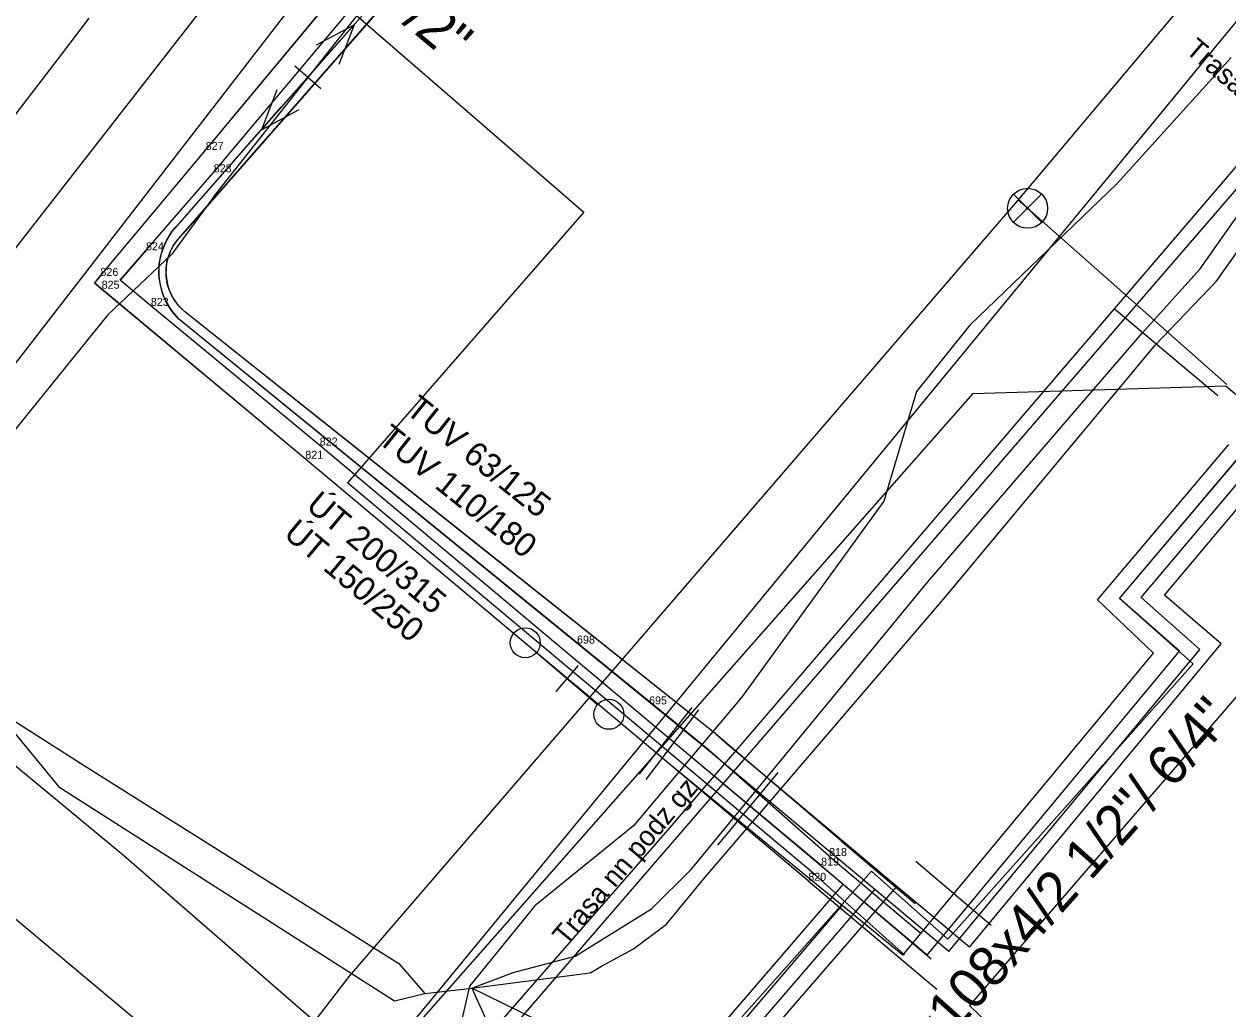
# Model space of a CAD drawing. Extents: x -494395 to -49419, y -1126982 to -112683.
# Drawn here: x -494321.11 to -494291.02, y -1126865.03 to -1126840.42 of the extents above; entities that cross this region are included whole.
import ezdxf

# ---------------------------------------------------------------- set-up
doc = ezdxf.new("R2010")
doc.units = 0
for name, color, linetype in [('Vrstva 1', 7, 'Continuous'), ('Vrstva 11', 7, 'Continuous'), ('Vrstva 12', 7, 'Continuous'), ('Vrstva 20', 7, 'Continuous'), ('Vrstva 22', 7, 'Continuous'), ('Vrstva 35', 7, 'Continuous'), ('Vrstva 37', 7, 'Continuous'), ('Vrstva 41', 7, 'Continuous'), ('Vrstva 45', 7, 'Continuous'), ('Vrstva 49', 7, 'Continuous'), ('Vrstva 5', 7, 'Continuous'), ('Vrstva 9', 7, 'Continuous')]:
    doc.layers.add(name, color=color, linetype=linetype)

msp = doc.modelspace()

# ---------------------------------------------------------------- linework, layer by layer
at = {"layer": 'Vrstva 1'}
msp.add_line((-494291.28, -1126849.71), (-494293.87, -1126847.53), dxfattribs=at)
for points in [[(-494360.93, -1126825.46), (-494336.61, -1126847.07), (-494335.52, -1126848.04), (-494331.63, -1126851.49), (-494328.43, -1126854.34), (-494326.87, -1126852.55), (-494322.66, -1126847.73), (-494316.57, -1126839.92), (-494313.81, -1126836.37), (-494313.37, -1126835.81), (-494312.74, -1126831.04), (-494296.98, -1126813.46), (-494295.26, -1126811.1), (-494294.71, -1126810.42), (-494294.273, -1126809.878)], [(-494274.427, -1126824.329), (-494280.54, -1126831.95), (-494293.87, -1126847.53), (-494302.1, -1126857.15), (-494305.03, -1126860.56), (-494313.03, -1126869.73)], [(-494328.43, -1126854.34), (-494329.69, -1126855.78), (-494325.53, -1126859.26), (-494313.03, -1126869.73), (-494305.67, -1126875.89), (-494291.14, -1126888.24), (-494277.78, -1126899.58), (-494263.78, -1126911.3)]]:
    msp.add_lwpolyline(points, dxfattribs=at)
at = {"layer": 'Vrstva 11'}
for points in [[(-494355.1, -1126829.18), (-494344.74, -1126839.16), (-494336.23, -1126846.61), (-494318.62, -1126861.19), (-494312.35, -1126866.64), (-494297.39, -1126849.65), (-494291.08, -1126849.46), (-494282.68, -1126856.57), (-494286.52, -1126861.18)], [(-494287.06, -1126860.73), (-494274.54, -1126845.74), (-494282.39, -1126839.2), (-494284.71, -1126837.46), (-494309.28, -1126865.93)], [(-494305.88, -1126863.53), (-494305.05, -1126862.91), (-494304.09, -1126861.74), (-494301.68, -1126858.93), (-494298.13, -1126854.79), (-494293.99, -1126849.82), (-494292.84, -1126848.44), (-494291.32, -1126846.85), (-494288.75, -1126843.24)], [(-494321.87, -1126857.51), (-494320.24, -1126859.48), (-494311.85, -1126864.83), (-494311.09, -1126864.65)], [(-494306.68, -1126863.96), (-494305.88, -1126863.53)], [(-494309.92, -1126864.51), (-494306.96, -1126864.13), (-494306.68, -1126863.96)], [(-494309.92, -1126864.51), (-494309.28, -1126865.93)], [(-494307.98, -1126865.46), (-494309.92, -1126864.51)]]:
    msp.add_lwpolyline(points, dxfattribs=at)
at = {"layer": 'Vrstva 12'}
for points in [[(-494309.92, -1126864.51), (-494308.89, -1126864.12), (-494307.34, -1126863.71), (-494305.43, -1126862.53), (-494304.44, -1126861.55), (-494302.04, -1126858.63), (-494298.52, -1126854.36), (-494294.37, -1126849.53), (-494293.17, -1126848.14), (-494291.72, -1126846.53), (-494289.12, -1126842.84), (-494287.01, -1126840.81), (-494284.04, -1126837.24), (-494280.15, -1126832.84), (-494279.04, -1126831.59), (-494278.24, -1126830.51), (-494275.18, -1126826.51), (-494273.746, -1126824.825)], [(-494321.87, -1126857.51), (-494319.61, -1126858.95)], [(-494319.61, -1126858.95), (-494311.74, -1126863.9)], [(-494311.74, -1126863.9), (-494311.09, -1126864.65)], [(-494311.09, -1126864.65), (-494309.92, -1126864.51)]]:
    msp.add_lwpolyline(points, dxfattribs=at)
at = {"layer": 'Vrstva 20'}
for points in [[(-494292.524, -1126811.151), (-494292.619, -1126811.279), (-494299.712, -1126820.924), (-494325.277, -1126853.999), (-494328.623, -1126858.84)], [(-494316.901, -1126869.31), (-494312.976, -1126864.212), (-494296.263, -1126844.814), (-494282.714, -1126828.712), (-494277.399, -1126822.165)], [(-494291.048, -1126849.423), (-494296.03, -1126845.02), (-494296.263, -1126844.814)]]:
    msp.add_lwpolyline(points, dxfattribs=at)
at = {"layer": 'Vrstva 22'}
for p, q in [((-494296.38, -1126845.37), (-494295.68, -1126844.67)), ((-494295.68, -1126845.37), (-494296.38, -1126844.67))]:
    msp.add_line(p, q, dxfattribs=at)
for radius in [0.5, 0.025]:
    msp.add_circle((-494296.03, -1126845.02), radius, dxfattribs=at)
at = {"layer": 'Vrstva 35'}
msp.add_lwpolyline([(-494300.66, -1126826.53), (-494304.08, -1126829.77), (-494307, -1126833.05), (-494310.38, -1126837.7), (-494312.57, -1126839.92), (-494316.3, -1126844.63), (-494317.42, -1126846.17), (-494319.02, -1126847.69), (-494327.08, -1126857.66), (-494327.96, -1126857.89), (-494330.7, -1126861.76), (-494332.02, -1126864.51), (-494334.7, -1126868.68), (-494331.75, -1126870.74), (-494343.19, -1126889.21), (-494346.12, -1126887.28)], dxfattribs=at)
at = {"layer": 'Vrstva 37'}
msp.add_lwpolyline([(-494267.04, -1126829.708), (-494297.48, -1126864.95), (-494274.68, -1126887.05), (-494269.33, -1126885.62)], dxfattribs=at)
at = {"layer": 'Vrstva 41'}
msp.add_lwpolyline([(-494276.436, -1126822.866), (-494276.44, -1126822.87), (-494321.46, -1126877.59)], dxfattribs=at)
at = {"layer": 'Vrstva 45'}
for p, q in [((-494316.57, -1126843.56), (-494308.89, -1126834.33)), ((-494316.57, -1126843.56), (-494308.89, -1126834.34)), ((-494316.37, -1126844.12), (-494308.66, -1126834.92)), ((-494316.37, -1126844.12), (-494308.66, -1126834.92)), ((-494314.68, -1126842.49), (-494308.31, -1126835.27)), ((-494312.93, -1126840.85), (-494308.15, -1126835.39)), ((-494310.93, -1126838.57), (-494317.14, -1126845.66)), ((-494313.94, -1126839.21), (-494307.12, -1126845.12)), ((-494315.175, -1126843.055), (-494312.86, -1126840.43)), ((-494317.14, -1126845.66), (-494312.93, -1126840.85)), ((-494314.339, -1126841.459), (-494313.696, -1126842.028)), ((-494317.22, -1126845.38), (-494314.68, -1126842.49)), ((-494317.22, -1126845.38), (-494315.23, -1126843.12)), ((-494319.2, -1126846.71), (-494316.57, -1126843.56)), ((-494319.2, -1126846.71), (-494316.57, -1126843.56)), ((-494316.57, -1126843.56), (-494316.57, -1126843.56)), ((-494318.06, -1126846.07), (-494316.37, -1126844.12)), ((-494318.06, -1126846.07), (-494316.37, -1126844.12)), ((-494316.37, -1126844.12), (-494316.37, -1126844.12)), ((-494307.4, -1126844.64), (-494307.4, -1126844.64)), ((-494307.12, -1126845.12), (-494313.03, -1126851.88)), ((-494317.56, -1126845.85), (-494317.41, -1126845.6)), ((-494317.41, -1126845.6), (-494317.22, -1126845.38)), ((-494317.27, -1126845.8), (-494317.14, -1126845.66)), ((-494317.25, -1126845.4), (-494317.25, -1126845.4)), ((-494317.14, -1126845.66), (-494317.14, -1126845.66)), ((-494317.67, -1126846.12), (-494317.56, -1126845.85)), ((-494317.47, -1126846.13), (-494317.38, -1126845.96)), ((-494317.38, -1126845.96), (-494317.27, -1126845.8)), ((-494307.8, -1126845.9), (-494307.8, -1126845.9)), ((-494318.06, -1126846.07), (-494318.71, -1126846.82)), ((-494318.71, -1126846.82), (-494318.06, -1126846.07)), ((-494318.06, -1126846.07), (-494318.06, -1126846.07)), ((-494317.73, -1126846.41), (-494317.67, -1126846.12)), ((-494317.53, -1126846.32), (-494317.47, -1126846.13)), ((-494317.74, -1126846.7), (-494317.73, -1126846.41)), ((-494317.56, -1126846.51), (-494317.53, -1126846.32)), ((-494317.56, -1126846.7), (-494317.56, -1126846.51)), ((-494319.2, -1126846.71), (-494319.35, -1126846.88)), ((-494319.35, -1126846.89), (-494319.2, -1126846.71)), ((-494319.2, -1126846.71), (-494319.2, -1126846.71)), ((-494317.94, -1126847.46), (-494318.71, -1126846.82)), ((-494318.71, -1126846.82), (-494318.71, -1126846.82)), ((-494317.94, -1126847.46), (-494318.71, -1126846.82)), ((-494317.74, -1126846.7), (-494317.74, -1126846.7)), ((-494317.7, -1126846.94), (-494317.74, -1126846.7)), ((-494317.56, -1126846.7), (-494317.56, -1126846.7)), ((-494317.53, -1126846.91), (-494317.56, -1126846.7)), ((-494319.17, -1126847.03), (-494319.35, -1126846.88)), ((-494319.35, -1126846.88), (-494319.35, -1126846.88)), ((-494319.17, -1126847.04), (-494319.35, -1126846.89)), ((-494319.17, -1126847.03), (-494319.17, -1126847.03)), ((-494314.08, -1126851.28), (-494319.17, -1126847.03)), ((-494314.08, -1126851.28), (-494319.17, -1126847.04)), ((-494317.64, -1126847.17), (-494317.7, -1126846.94)), ((-494317.54, -1126847.4), (-494317.64, -1126847.17)), ((-494317.47, -1126847.1), (-494317.53, -1126846.91)), ((-494317.37, -1126847.29), (-494317.47, -1126847.1)), ((-494313.72, -1126850.95), (-494317.94, -1126847.46)), ((-494317.94, -1126847.46), (-494317.94, -1126847.46)), ((-494313.72, -1126850.95), (-494317.94, -1126847.46)), ((-494317.41, -1126847.6), (-494317.54, -1126847.4)), ((-494317.25, -1126847.45), (-494317.37, -1126847.29)), ((-494317.1, -1126847.6), (-494317.25, -1126847.45)), ((-494317.25, -1126847.78), (-494317.41, -1126847.6)), ((-494303.89, -1126858.11), (-494317.1, -1126847.6)), ((-494317.1, -1126847.6), (-494317.1, -1126847.6)), ((-494309.74, -1126853.46), (-494317.1, -1126847.6)), ((-494304.06, -1126858.51), (-494317.25, -1126847.78)), ((-494317.25, -1126847.78), (-494317.25, -1126847.78)), ((-494304.06, -1126858.52), (-494317.25, -1126847.78)), ((-494313.72, -1126850.95), (-494313.72, -1126850.95)), ((-494304.52, -1126858.66), (-494313.72, -1126850.95)), ((-494304.52, -1126858.66), (-494313.72, -1126850.95)), ((-494312.25, -1126850.99), (-494312.25, -1126850.99)), ((-494294.28, -1126854.81), (-494291, -1126850.92)), ((-494293.73, -1126854.77), (-494290.45, -1126850.89)), ((-494293.19, -1126854.75), (-494289.91, -1126850.85)), ((-494292.61, -1126854.69), (-494289.36, -1126850.82)), ((-494314.08, -1126851.28), (-494314.08, -1126851.28)), ((-494308.95, -1126855.58), (-494314.08, -1126851.28)), ((-494304.89, -1126858.99), (-494314.08, -1126851.28)), ((-494301.35, -1126861.67), (-494313.03, -1126851.88)), ((-494312.45, -1126852.38), (-494312.45, -1126852.38)), ((-494303.89, -1126858.11), (-494309.74, -1126853.46)), ((-494291.19, -1126855.91), (-494292.61, -1126854.69)), ((-494292.88, -1126856.14), (-494294.28, -1126854.81)), ((-494293.73, -1126854.77), (-494291.89, -1126856.41)), ((-494292.23, -1126856.09), (-494293.73, -1126854.77)), ((-494291.73, -1126856.05), (-494293.19, -1126854.75)), ((-494308.3, -1126856.123), (-494306.78, -1126857.421)), ((-494307.29, -1126855.9), (-494307.29, -1126855.9)), ((-494299.15, -1126863.69), (-494292.88, -1126856.14)), ((-494298.54, -1126863.69), (-494292.23, -1126856.09)), ((-494298, -1126863.6), (-494291.73, -1126856.05)), ((-494297.48, -1126863.49), (-494291.19, -1126855.91)), ((-494307.26, -1126856.446), (-494307.819, -1126857.1)), ((-494298.02, -1126863.29), (-494291.89, -1126856.41)), ((-494304.42, -1126857.5), (-494305.74, -1126859.16)), ((-494305.56, -1126859.3), (-494304.25, -1126857.56)), ((-494305.49, -1126857.42), (-494305.49, -1126857.42)), ((-494304.89, -1126858.99), (-494306.12, -1126857.96)), ((-494306.06, -1126857.88), (-494306.06, -1126857.88)), ((-494300.68, -1126860.84), (-494303.89, -1126858.11)), ((-494303.89, -1126858.11), (-494303.89, -1126858.11)), ((-494303.53, -1126858.42), (-494303.89, -1126858.11)), ((-494300.99, -1126861.21), (-494304.06, -1126858.51)), ((-494304.06, -1126858.51), (-494304.06, -1126858.51)), ((-494299.85, -1126862.05), (-494304.06, -1126858.52)), ((-494299.3, -1126861.97), (-494303.53, -1126858.42)), ((-494301.19, -1126861.45), (-494304.52, -1126858.66)), ((-494304.52, -1126858.66), (-494304.52, -1126858.66)), ((-494300.64, -1126861.92), (-494304.52, -1126858.66)), ((-494301.51, -1126861.83), (-494304.89, -1126858.99)), ((-494304.89, -1126858.99), (-494304.89, -1126858.99)), ((-494300.66, -1126862.45), (-494304.89, -1126858.99)), ((-494303.77, -1126860.94), (-494302.26, -1126859.12)), ((-494300.99, -1126861.21), (-494300.99, -1126861.21)), ((-494305.8, -1126868.18), (-494299.93, -1126861.59)), ((-494301.43, -1126861.61), (-494301.43, -1126861.61)), ((-494301.19, -1126861.45), (-494301.19, -1126861.45)), ((-494299.93, -1126861.59), (-494298.02, -1126863.29)), ((-494301.51, -1126861.83), (-494301.51, -1126861.83)), ((-494300.6, -1126862.35), (-494301.35, -1126861.67)), ((-494304.36, -1126866.24), (-494300.64, -1126861.92)), ((-494304.07, -1126866.95), (-494299.85, -1126862.05)), ((-494303.74, -1126867.1), (-494299.3, -1126861.97)), ((-494298.54, -1126863.69), (-494300.64, -1126861.92)), ((-494298, -1126863.6), (-494299.85, -1126862.05)), ((-494297.48, -1126863.49), (-494299.3, -1126861.97)), ((-494304.26, -1126866.65), (-494300.66, -1126862.45)), ((-494299.15, -1126863.69), (-494300.66, -1126862.45)), ((-494299.11, -1126863.68), (-494300.6, -1126862.35))]:
    msp.add_line(p, q, dxfattribs=at)
for points in [[(-494313.803, -1126840.932), (-494312.86, -1126840.43), (-494313.24, -1126841.427)], [(-494314.794, -1126842.056), (-494315.175, -1126843.055), (-494314.232, -1126842.553)], [(-494293.73, -1126854.77), (-494283.26, -1126842.41)]]:
    msp.add_lwpolyline(points, dxfattribs=at)
for centre in [(-494308.584, -1126855.88), (-494306.495, -1126857.668)]:
    msp.add_circle(centre, 0.375, dxfattribs=at)
for centre, radius, start, end in [((-494316.049, -1126846.604), 1.694, 133.7411, 183.2561), ((-494316.258, -1126846.621), 1.305, 132.5481, 183.4697), ((-494316.062, -1126846.59), 1.682, 183.7609, 225.0471), ((-494316.285, -1126846.616), 1.278, 183.7826, 230.3615)]:
    msp.add_arc(centre, radius, start, end, dxfattribs=at)
at = {"layer": 'Vrstva 49'}
for p, q in [((-494300.68, -1126860.84), (-494298.84, -1126862.4)), ((-494300.99, -1126861.21), (-494298.69, -1126863.15)), ((-494301.19, -1126861.45), (-494298.44, -1126863.78)), ((-494298.82, -1126861.34), (-494296.94, -1126862.94)), ((-494301.51, -1126861.83), (-494298.3, -1126864.54))]:
    msp.add_line(p, q, dxfattribs=at)
at = {"layer": 'Vrstva 5'}
for points in [[(-494334.819, -1126859.137), (-494334.405, -1126858.477), (-494332.038, -1126855.399), (-494327.363, -1126850.088), (-494321.788, -1126843.277), (-494320.277, -1126841.306), (-494319.485, -1126840.271)], [(-494290.944, -1126841.251), (-494293.803, -1126844.41), (-494297.475, -1126847.939), (-494298.803, -1126849.6), (-494299.62, -1126852.341), (-494303.181, -1126857.248), (-494305.877, -1126860.459), (-494308.341, -1126862.457), (-494309.981, -1126864.466), (-494310.59, -1126867.15), (-494310.629, -1126870.07), (-494311.184, -1126871.451), (-494316.519, -1126878.222), (-494317.129, -1126878.573), (-494319.457, -1126878.505)]]:
    msp.add_lwpolyline(points, dxfattribs=at)

# ---------------------------------------------------------------- texts
at = {"layer": 'Vrstva 49'}
for s, height, rotation, p in [('2x219x6/3" /2"', 1, 320.2343, (-494317.068, -1126835.907)), ('TUV 63/125', 0.6, 321.4769, (-494311.604, -1126850.121)), ('TUV 110/180', 0.6, 321.4769, (-494312.303, -1126850.851)), ('ÚT 200/315', 0.6, 320.0104, (-494314.092, -1126852.507)), ('ÚT 150/250', 0.6, 320.0104, (-494314.652, -1126853.207)), ('2x108x4/2 1/2"/ 6/4"', 1, 48.2973, (-494298.809, -1126866.732))]:
    msp.add_text(s, height=height, rotation=rotation, dxfattribs=at).set_placement(p)
for s, p in [('827', (-494316.57, -1126843.56)), ('828', (-494316.37, -1126844.12)), ('824', (-494318.06, -1126846.07)), ('826', (-494319.2, -1126846.71)), ('825', (-494319.17, -1126847.03)), ('823', (-494317.94, -1126847.46)), ('822', (-494313.72, -1126850.95)), ('821', (-494314.08, -1126851.28)), ('698', (-494307.29, -1126855.9)), ('695', (-494305.49, -1126857.42)), ('818', (-494300.99, -1126861.21)), ('819', (-494301.19, -1126861.45)), ('820', (-494301.51, -1126861.83))]:
    msp.add_text(s, height=0.2, dxfattribs=at).set_placement(p)
at = {"layer": 'Vrstva 9'}
for rotation, p in [(319.444, (-494292.11, -1126841.108)), (49.9827, (-494307.562, -1126863.477))]:
    msp.add_text('Trasa nn podz gz', height=0.5, rotation=rotation, dxfattribs=at).set_placement(p)

doc.saveas('drawing.dxf')
